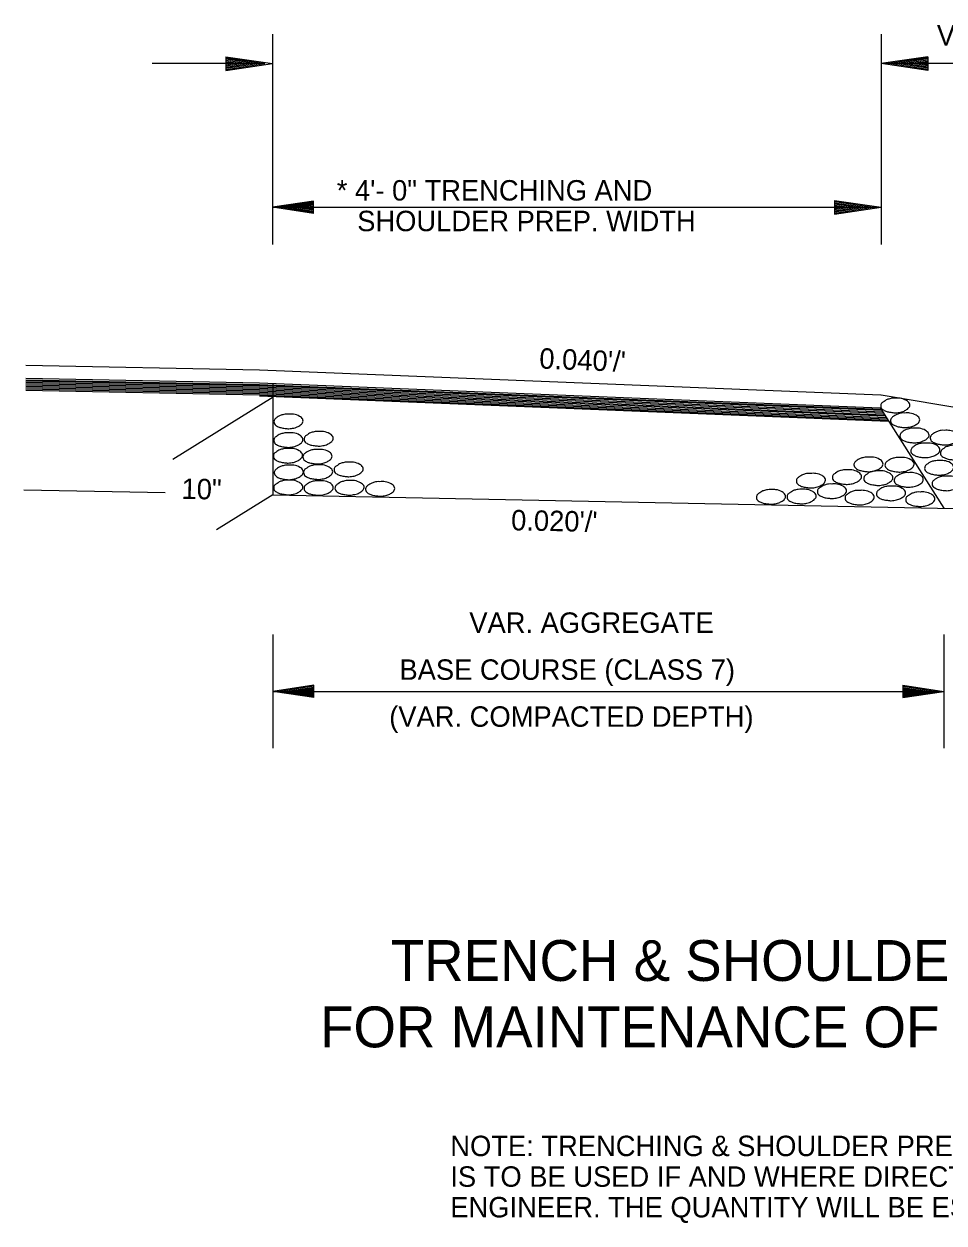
# Model space of a CAD drawing. Extents: x 1929624 to 1935547, y 596315 to 605721.
# Drawn here: x 1932720.6 to 1932990.8, y 604122.9 to 604475 of the extents above; entities that cross this region are included whole.
import ezdxf

# ---------------------------------------------------------------- set-up
doc = ezdxf.new("R2010")
doc.units = 0
doc.layers.add('Default', color=7, linetype='Continuous')
doc.layers.add('R_Border', color=7, linetype='Continuous')

msp = doc.modelspace()

# ---------------------------------------------------------------- linework, layer by layer
at = {"layer": 'Default'}
for p, q in [((1932793.63, 604472.05), (1932793.63, 604410.28)), ((1932972.32, 604472.05), (1932972.32, 604410.28)), ((1932791.33, 604463.38), (1932758.3, 604463.38)), ((1932779.9, 604465.42), (1932793.6, 604463.38)), ((1932779.9, 604465.42), (1932779.9, 604461.32)), ((1932779.9, 604465.09), (1932791.33, 604463.38)), ((1932779.9, 604464.74), (1932788.96, 604463.38)), ((1932779.9, 604464.41), (1932786.68, 604463.38)), ((1932779.9, 604464.02), (1932784.36, 604463.38)), ((1932779.9, 604463.71), (1932782.09, 604463.38)), ((1932779.9, 604461.32), (1932793.6, 604463.38)), ((1932779.9, 604462.7), (1932784.36, 604463.38)), ((1932779.9, 604462.01), (1932788.96, 604463.38)), ((1932779.9, 604461.67), (1932791.33, 604463.38)), ((1932779.9, 604462.37), (1932786.68, 604463.38)), ((1932779.9, 604463.05), (1932782.09, 604463.38)), ((1932986.02, 604465.42), (1932972.32, 604463.38)), ((1932986.02, 604461.32), (1932972.32, 604463.38)), ((1933213.06, 604463.38), (1932972.32, 604463.38)), ((1932986.02, 604465.09), (1932974.59, 604463.38)), ((1932986.02, 604461.67), (1932974.59, 604463.38)), ((1932986.02, 604464.74), (1932976.96, 604463.38)), ((1932986.02, 604462.01), (1932976.96, 604463.38)), ((1932986.02, 604464.41), (1932979.24, 604463.38)), ((1932986.02, 604462.37), (1932979.24, 604463.38)), ((1932986.02, 604464.02), (1932981.56, 604463.38)), ((1932986.02, 604462.7), (1932981.56, 604463.38)), ((1932986.02, 604463.71), (1932983.83, 604463.38)), ((1932986.02, 604463.05), (1932983.83, 604463.38)), ((1932986.02, 604465.42), (1932986.02, 604461.32)), ((1932805.63, 604422.99), (1932793.63, 604421.19)), ((1932793.63, 604421.19), (1932972.32, 604421.19)), ((1932805.63, 604419.39), (1932793.63, 604421.19)), ((1932805.63, 604422.69), (1932795.63, 604421.19)), ((1932805.63, 604419.69), (1932795.63, 604421.19)), ((1932805.63, 604422.38), (1932797.7, 604421.19)), ((1932805.63, 604420), (1932797.7, 604421.19)), ((1932805.63, 604422.08), (1932799.7, 604421.19)), ((1932805.63, 604420.3), (1932799.7, 604421.19)), ((1932805.63, 604421.78), (1932801.73, 604421.19)), ((1932805.63, 604420.61), (1932801.73, 604421.19)), ((1932805.63, 604421.47), (1932803.73, 604421.19)), ((1932805.63, 604420.91), (1932803.73, 604421.19)), ((1932805.63, 604419.39), (1932805.63, 604422.99)), ((1932958.64, 604423.23), (1932972.32, 604421.19)), ((1932958.64, 604423.23), (1932958.64, 604419.13)), ((1932958.64, 604422.9), (1932970.03, 604421.19)), ((1932958.64, 604422.54), (1932967.69, 604421.19)), ((1932958.64, 604422.21), (1932965.42, 604421.19)), ((1932958.64, 604421.84), (1932963.06, 604421.19)), ((1932958.64, 604421.51), (1932960.79, 604421.19)), ((1932958.64, 604419.13), (1932972.32, 604421.19)), ((1932958.64, 604420.5), (1932963.06, 604421.19)), ((1932958.64, 604419.81), (1932967.69, 604421.19)), ((1932958.64, 604419.47), (1932970.03, 604421.19)), ((1932958.64, 604420.17), (1932965.42, 604421.19)), ((1932958.64, 604420.86), (1932960.79, 604421.19)), ((1932972.32, 604417.14), (1932972.32, 604410.28)), ((1932721.2, 604374.81), (1932789.81, 604373.44)), ((1932721.2, 604370.99), (1932789.81, 604369.64)), ((1932789.81, 604373.44), (1932972.2, 604366.13)), ((1932721.2, 604370.57), (1932789.81, 604369.2)), ((1932721.2, 604370.25), (1932789.81, 604368.87)), ((1932721.2, 604369.84), (1932789.81, 604368.45)), ((1932721.2, 604369.44), (1932789.81, 604368.03)), ((1932721.2, 604369.06), (1932789.81, 604367.67)), ((1932721.2, 604368.67), (1932789.81, 604367.29)), ((1932721.2, 604368.28), (1932789.81, 604366.91)), ((1932721.2, 604367.85), (1932789.81, 604366.49)), ((1932721.2, 604367.47), (1932789.81, 604366.12)), ((1932789.81, 604369.64), (1932972.04, 604362.31)), ((1932789.81, 604369.2), (1932972.32, 604361.86)), ((1932789.81, 604368.87), (1932972.51, 604361.57)), ((1932789.81, 604368.45), (1932972.82, 604361.11)), ((1932789.81, 604368.03), (1932973.04, 604360.71)), ((1932789.81, 604367.67), (1932973.32, 604360.27)), ((1932789.81, 604367.29), (1932973.54, 604359.93)), ((1932793.72, 604369.49), (1932793.72, 604336.78)), ((1932793.76, 604365.44), (1932764.33, 604347.1)), ((1932789.81, 604366.91), (1932973.86, 604359.49)), ((1932789.81, 604366.49), (1932974.1, 604359.09)), ((1932789.81, 604366.12), (1932974.36, 604358.65)), ((1932789.81, 604365.79), (1932974.53, 604358.37)), ((1932972.32, 604366.13), (1933363.55, 604300.92)), ((1932972.04, 604362.31), (1932990.74, 604332.85)), ((1932720.62, 604338.25), (1932762.1, 604337.42)), ((1932793.72, 604336.78), (1932777.18, 604326.47)), ((1932793.72, 604336.78), (1933196.64, 604328.73)), ((1932793.72, 604295.7), (1932793.72, 604262.34)), ((1932990.74, 604295.7), (1932990.74, 604262.34)), ((1932805.72, 604280.82), (1932793.72, 604279.02)), ((1932805.72, 604280.52), (1932795.72, 604279.02)), ((1932805.72, 604280.21), (1932797.79, 604279.02)), ((1932805.72, 604279.91), (1932799.79, 604279.02)), ((1932805.72, 604279.61), (1932801.82, 604279.02)), ((1932805.72, 604279.3), (1932803.82, 604279.02)), ((1932805.72, 604277.22), (1932805.72, 604280.82)), ((1932978.74, 604280.82), (1932990.74, 604279.02)), ((1932978.74, 604280.82), (1932978.74, 604277.22)), ((1932978.74, 604280.52), (1932988.74, 604279.02)), ((1932978.74, 604280.21), (1932986.67, 604279.02)), ((1932978.74, 604279.91), (1932984.67, 604279.02)), ((1932978.74, 604279.6), (1932982.64, 604279.02)), ((1932978.74, 604279.3), (1932980.64, 604279.02)), ((1932793.72, 604279.02), (1932990.74, 604279.02)), ((1932805.72, 604277.22), (1932793.72, 604279.02)), ((1932805.72, 604277.52), (1932795.72, 604279.02)), ((1932805.72, 604277.83), (1932797.79, 604279.02)), ((1932805.72, 604278.13), (1932799.79, 604279.02)), ((1932805.72, 604278.44), (1932801.82, 604279.02)), ((1932805.72, 604278.74), (1932803.82, 604279.02)), ((1932978.74, 604277.22), (1932990.74, 604279.02)), ((1932978.74, 604278.43), (1932982.64, 604279.02)), ((1932978.74, 604277.83), (1932986.67, 604279.02)), ((1932978.74, 604277.52), (1932988.74, 604279.02)), ((1932978.74, 604278.13), (1932984.67, 604279.02)), ((1932978.74, 604278.74), (1932980.64, 604279.02))]:
    msp.add_line(p, q, dxfattribs=at)
for points in [[(1932976.42, 604365.1), (1932977.95, 604365.09), (1932979.77, 604364.45), (1932980.66, 604363.62), (1932980.78, 604363.08), (1932980.32, 604362.16), (1932979.8, 604361.77), (1932978.8, 604361.25), (1932977.34, 604360.91), (1932976.58, 604360.83), (1932975.47, 604360.94), (1932974.21, 604361.15), (1932973.26, 604361.52), (1932972.38, 604362.25), (1932972.23, 604362.83), (1932972.49, 604363.65), (1932973.19, 604364.18), (1932973.83, 604364.6), (1932974.85, 604364.95), (1932975.48, 604365.09), (1932976.42, 604365.1)], [(1932798.22, 604360.43), (1932799.75, 604360.42), (1932801.57, 604359.78), (1932802.46, 604358.95), (1932802.58, 604358.41), (1932802.12, 604357.49), (1932801.6, 604357.1), (1932800.6, 604356.58), (1932799.14, 604356.24), (1932798.38, 604356.16), (1932797.27, 604356.27), (1932796.01, 604356.48), (1932795.06, 604356.85), (1932794.18, 604357.58), (1932794.03, 604358.16), (1932794.29, 604358.98), (1932794.99, 604359.51), (1932795.63, 604359.93), (1932796.65, 604360.28), (1932797.28, 604360.42), (1932798.22, 604360.43)], [(1932979.3, 604360.77), (1932980.8, 604360.76), (1932982.62, 604360.12), (1932983.54, 604359.28), (1932983.67, 604358.75), (1932983.18, 604357.83), (1932982.64, 604357.41), (1932981.69, 604356.91), (1932980.17, 604356.6), (1932979.44, 604356.49), (1932978.3, 604356.61), (1932977.09, 604356.81), (1932976.15, 604357.2), (1932975.25, 604357.89), (1932975.09, 604358.5), (1932975.38, 604359.31), (1932976.06, 604359.87), (1932976.72, 604360.29), (1932977.7, 604360.6), (1932978.32, 604360.76), (1932979.3, 604360.77)], [(1932798.18, 604354.95), (1932799.71, 604354.94), (1932801.53, 604354.3), (1932802.42, 604353.47), (1932802.54, 604352.93), (1932802.08, 604352.01), (1932801.56, 604351.62), (1932800.56, 604351.1), (1932799.1, 604350.76), (1932798.34, 604350.68), (1932797.23, 604350.79), (1932795.97, 604351), (1932795.02, 604351.37), (1932794.14, 604352.1), (1932793.99, 604352.68), (1932794.25, 604353.5), (1932794.95, 604354.03), (1932795.59, 604354.45), (1932796.61, 604354.8), (1932797.24, 604354.94), (1932798.18, 604354.95)], [(1932807.08, 604355.33), (1932808.61, 604355.32), (1932810.43, 604354.68), (1932811.32, 604353.85), (1932811.44, 604353.31), (1932810.98, 604352.39), (1932810.46, 604352), (1932809.46, 604351.48), (1932808, 604351.14), (1932807.24, 604351.06), (1932806.13, 604351.17), (1932804.87, 604351.38), (1932803.92, 604351.75), (1932803.04, 604352.48), (1932802.89, 604353.06), (1932803.15, 604353.88), (1932803.85, 604354.41), (1932804.49, 604354.83), (1932805.51, 604355.18), (1932806.14, 604355.32), (1932807.08, 604355.33)], [(1932982.06, 604356.3), (1932983.57, 604356.28), (1932985.38, 604355.66), (1932986.28, 604354.79), (1932986.44, 604354.29), (1932985.96, 604353.35), (1932985.43, 604352.93), (1932984.44, 604352.48), (1932982.96, 604352.09), (1932982.2, 604352.03), (1932981.08, 604352.11), (1932979.85, 604352.33), (1932978.9, 604352.71), (1932978.02, 604353.42), (1932977.87, 604354.02), (1932978.13, 604354.82), (1932978.82, 604355.4), (1932979.46, 604355.83), (1932980.49, 604356.14), (1932981.11, 604356.28), (1932982.06, 604356.3)], [(1932990.96, 604355.68), (1932992.47, 604355.66), (1932994.28, 604355.04), (1932995.2, 604354.16), (1932995.31, 604353.68), (1932994.85, 604352.73), (1932994.32, 604352.33), (1932993.34, 604351.84), (1932991.85, 604351.47), (1932991.1, 604351.41), (1932989.98, 604351.52), (1932988.75, 604351.72), (1932987.78, 604352.09), (1932986.91, 604352.82), (1932986.75, 604353.4), (1932987.02, 604354.21), (1932987.72, 604354.77), (1932988.36, 604355.19), (1932989.38, 604355.52), (1932989.99, 604355.66), (1932990.96, 604355.68)], [(1932798.06, 604350.35), (1932799.59, 604350.34), (1932801.41, 604349.7), (1932802.3, 604348.87), (1932802.42, 604348.33), (1932801.96, 604347.41), (1932801.44, 604347.02), (1932800.44, 604346.5), (1932798.98, 604346.16), (1932798.22, 604346.08), (1932797.11, 604346.19), (1932795.85, 604346.4), (1932794.9, 604346.77), (1932794.02, 604347.5), (1932793.87, 604348.08), (1932794.13, 604348.9), (1932794.83, 604349.43), (1932795.47, 604349.85), (1932796.49, 604350.2), (1932797.12, 604350.34), (1932798.06, 604350.35)], [(1932806.72, 604350.08), (1932808.25, 604350.07), (1932810.07, 604349.43), (1932810.96, 604348.6), (1932811.08, 604348.06), (1932810.62, 604347.14), (1932810.1, 604346.75), (1932809.1, 604346.23), (1932807.64, 604345.89), (1932806.88, 604345.81), (1932805.77, 604345.92), (1932804.51, 604346.13), (1932803.56, 604346.5), (1932802.68, 604347.23), (1932802.53, 604347.81), (1932802.79, 604348.63), (1932803.49, 604349.16), (1932804.13, 604349.58), (1932805.15, 604349.93), (1932805.78, 604350.07), (1932806.72, 604350.08)], [(1932985.27, 604351.92), (1932986.75, 604351.9), (1932988.59, 604351.31), (1932989.46, 604350.44), (1932989.62, 604349.94), (1932989.15, 604348.99), (1932988.61, 604348.59), (1932987.62, 604348.12), (1932986.16, 604347.74), (1932985.38, 604347.68), (1932984.27, 604347.76), (1932983.04, 604347.96), (1932982.09, 604348.37), (1932981.19, 604349.08), (1932981.06, 604349.65), (1932981.33, 604350.47), (1932982.01, 604351.02), (1932982.64, 604351.45), (1932983.67, 604351.8), (1932984.29, 604351.9), (1932985.27, 604351.92)], [(1932993.98, 604351.28), (1932995.46, 604351.27), (1932997.3, 604350.64), (1932998.17, 604349.77), (1932998.33, 604349.27), (1932997.86, 604348.34), (1932997.32, 604347.93), (1932996.33, 604347.45), (1932994.87, 604347.07), (1932994.09, 604347.03), (1932993, 604347.09), (1932991.75, 604347.29), (1932990.8, 604347.7), (1932989.91, 604348.4), (1932989.77, 604348.99), (1932990.05, 604349.82), (1932990.74, 604350.38), (1932991.35, 604350.81), (1932992.38, 604351.11), (1932993.02, 604351.27), (1932993.98, 604351.28)], [(1932815.88, 604346.33), (1932817.41, 604346.32), (1932819.23, 604345.68), (1932820.12, 604344.85), (1932820.24, 604344.31), (1932819.78, 604343.39), (1932819.26, 604343), (1932818.26, 604342.48), (1932816.8, 604342.14), (1932816.04, 604342.06), (1932814.93, 604342.17), (1932813.67, 604342.38), (1932812.72, 604342.75), (1932811.84, 604343.48), (1932811.69, 604344.06), (1932811.95, 604344.88), (1932812.65, 604345.41), (1932813.29, 604345.83), (1932814.31, 604346.18), (1932814.94, 604346.32), (1932815.88, 604346.33)], [(1932968.54, 604347.81), (1932970.07, 604347.8), (1932971.89, 604347.16), (1932972.78, 604346.33), (1932972.9, 604345.79), (1932972.44, 604344.87), (1932971.92, 604344.48), (1932970.92, 604343.96), (1932969.46, 604343.62), (1932968.7, 604343.54), (1932967.59, 604343.65), (1932966.33, 604343.86), (1932965.38, 604344.23), (1932964.5, 604344.96), (1932964.35, 604345.54), (1932964.61, 604346.36), (1932965.31, 604346.89), (1932965.95, 604347.31), (1932966.97, 604347.66), (1932967.6, 604347.8), (1932968.54, 604347.81)], [(1932977.66, 604347.71), (1932979.19, 604347.7), (1932981.01, 604347.06), (1932981.9, 604346.23), (1932982.02, 604345.69), (1932981.56, 604344.77), (1932981.04, 604344.38), (1932980.04, 604343.86), (1932978.58, 604343.52), (1932977.82, 604343.44), (1932976.71, 604343.55), (1932975.45, 604343.76), (1932974.5, 604344.13), (1932973.62, 604344.86), (1932973.47, 604345.44), (1932973.73, 604346.26), (1932974.43, 604346.79), (1932975.07, 604347.21), (1932976.09, 604347.56), (1932976.72, 604347.7), (1932977.66, 604347.71)], [(1932989.29, 604346.82), (1932990.83, 604346.78), (1932992.66, 604346.17), (1932993.55, 604345.3), (1932993.65, 604344.8), (1932993.19, 604343.85), (1932992.67, 604343.44), (1932991.69, 604342.96), (1932990.21, 604342.6), (1932989.45, 604342.54), (1932988.34, 604342.63), (1932987.12, 604342.85), (1932986.16, 604343.22), (1932985.27, 604343.93), (1932985.11, 604344.53), (1932985.38, 604345.36), (1932986.07, 604345.89), (1932986.72, 604346.33), (1932987.72, 604346.65), (1932988.36, 604346.78), (1932989.29, 604346.82)], [(1932798.31, 604345.46), (1932799.84, 604345.45), (1932801.66, 604344.81), (1932802.55, 604343.98), (1932802.67, 604343.44), (1932802.21, 604342.52), (1932801.69, 604342.13), (1932800.69, 604341.61), (1932799.23, 604341.27), (1932798.47, 604341.19), (1932797.36, 604341.3), (1932796.1, 604341.51), (1932795.15, 604341.88), (1932794.27, 604342.61), (1932794.12, 604343.19), (1932794.38, 604344.01), (1932795.08, 604344.54), (1932795.72, 604344.96), (1932796.74, 604345.31), (1932797.37, 604345.45), (1932798.31, 604345.46)], [(1932806.91, 604345.54), (1932808.44, 604345.53), (1932810.26, 604344.89), (1932811.15, 604344.06), (1932811.27, 604343.52), (1932810.81, 604342.6), (1932810.29, 604342.21), (1932809.29, 604341.69), (1932807.83, 604341.35), (1932807.07, 604341.27), (1932805.96, 604341.38), (1932804.7, 604341.59), (1932803.75, 604341.96), (1932802.87, 604342.69), (1932802.72, 604343.27), (1932802.98, 604344.09), (1932803.68, 604344.62), (1932804.32, 604345.04), (1932805.34, 604345.39), (1932805.97, 604345.53), (1932806.91, 604345.54)], [(1932951.63, 604343.04), (1932953.16, 604343.03), (1932954.98, 604342.39), (1932955.87, 604341.56), (1932955.99, 604341.02), (1932955.53, 604340.1), (1932955.01, 604339.71), (1932954.01, 604339.19), (1932952.55, 604338.85), (1932951.79, 604338.77), (1932950.68, 604338.88), (1932949.42, 604339.09), (1932948.47, 604339.46), (1932947.59, 604340.19), (1932947.44, 604340.77), (1932947.7, 604341.59), (1932948.4, 604342.12), (1932949.04, 604342.54), (1932950.06, 604342.89), (1932950.69, 604343.03), (1932951.63, 604343.04)], [(1932962.21, 604344.08), (1932963.74, 604344.07), (1932965.56, 604343.43), (1932966.45, 604342.6), (1932966.57, 604342.06), (1932966.11, 604341.14), (1932965.59, 604340.75), (1932964.59, 604340.23), (1932963.13, 604339.89), (1932962.37, 604339.81), (1932961.26, 604339.92), (1932960, 604340.13), (1932959.05, 604340.5), (1932958.17, 604341.23), (1932958.02, 604341.81), (1932958.28, 604342.63), (1932958.98, 604343.16), (1932959.62, 604343.58), (1932960.64, 604343.93), (1932961.27, 604344.07), (1932962.21, 604344.08)], [(1932971.44, 604343.77), (1932972.97, 604343.76), (1932974.79, 604343.12), (1932975.68, 604342.29), (1932975.8, 604341.75), (1932975.34, 604340.83), (1932974.82, 604340.44), (1932973.82, 604339.92), (1932972.36, 604339.58), (1932971.6, 604339.5), (1932970.49, 604339.61), (1932969.23, 604339.82), (1932968.28, 604340.19), (1932967.4, 604340.92), (1932967.25, 604341.5), (1932967.51, 604342.32), (1932968.21, 604342.85), (1932968.85, 604343.27), (1932969.87, 604343.62), (1932970.5, 604343.76), (1932971.44, 604343.77)], [(1932980.36, 604343.25), (1932981.89, 604343.24), (1932983.71, 604342.6), (1932984.6, 604341.77), (1932984.72, 604341.23), (1932984.26, 604340.31), (1932983.74, 604339.92), (1932982.74, 604339.4), (1932981.28, 604339.06), (1932980.52, 604338.98), (1932979.41, 604339.09), (1932978.15, 604339.3), (1932977.2, 604339.67), (1932976.32, 604340.4), (1932976.17, 604340.98), (1932976.43, 604341.8), (1932977.13, 604342.33), (1932977.77, 604342.75), (1932978.79, 604343.1), (1932979.42, 604343.24), (1932980.36, 604343.25)], [(1932798.15, 604341.02), (1932799.68, 604341.01), (1932801.5, 604340.37), (1932802.39, 604339.54), (1932802.51, 604339), (1932802.05, 604338.08), (1932801.53, 604337.69), (1932800.53, 604337.17), (1932799.07, 604336.83), (1932798.31, 604336.75), (1932797.2, 604336.86), (1932795.94, 604337.07), (1932794.99, 604337.44), (1932794.11, 604338.17), (1932793.96, 604338.75), (1932794.22, 604339.57), (1932794.92, 604340.1), (1932795.56, 604340.52), (1932796.58, 604340.87), (1932797.21, 604341.01), (1932798.15, 604341.02)], [(1932807.07, 604340.88), (1932808.6, 604340.87), (1932810.42, 604340.23), (1932811.31, 604339.4), (1932811.43, 604338.86), (1932810.97, 604337.94), (1932810.45, 604337.55), (1932809.45, 604337.03), (1932807.99, 604336.69), (1932807.23, 604336.61), (1932806.12, 604336.72), (1932804.86, 604336.93), (1932803.91, 604337.3), (1932803.03, 604338.03), (1932802.88, 604338.61), (1932803.14, 604339.43), (1932803.84, 604339.96), (1932804.48, 604340.38), (1932805.5, 604340.73), (1932806.13, 604340.87), (1932807.07, 604340.88)], [(1932816.14, 604340.93), (1932817.67, 604340.92), (1932819.49, 604340.28), (1932820.38, 604339.45), (1932820.5, 604338.91), (1932820.04, 604337.99), (1932819.52, 604337.6), (1932818.52, 604337.08), (1932817.06, 604336.74), (1932816.3, 604336.66), (1932815.19, 604336.77), (1932813.93, 604336.98), (1932812.98, 604337.35), (1932812.1, 604338.08), (1932811.95, 604338.66), (1932812.21, 604339.48), (1932812.91, 604340.01), (1932813.55, 604340.43), (1932814.57, 604340.78), (1932815.2, 604340.92), (1932816.14, 604340.93)], [(1932825.13, 604340.61), (1932826.66, 604340.6), (1932828.48, 604339.96), (1932829.37, 604339.13), (1932829.49, 604338.59), (1932829.03, 604337.67), (1932828.51, 604337.28), (1932827.51, 604336.76), (1932826.05, 604336.42), (1932825.29, 604336.34), (1932824.18, 604336.45), (1932822.92, 604336.66), (1932821.97, 604337.03), (1932821.09, 604337.76), (1932820.94, 604338.34), (1932821.2, 604339.16), (1932821.9, 604339.69), (1932822.54, 604340.11), (1932823.56, 604340.46), (1932824.19, 604340.6), (1932825.13, 604340.61)], [(1932957.81, 604339.93), (1932959.34, 604339.92), (1932961.16, 604339.28), (1932962.05, 604338.45), (1932962.17, 604337.91), (1932961.71, 604336.99), (1932961.19, 604336.6), (1932960.19, 604336.08), (1932958.73, 604335.74), (1932957.97, 604335.66), (1932956.86, 604335.77), (1932955.6, 604335.98), (1932954.65, 604336.35), (1932953.77, 604337.08), (1932953.62, 604337.66), (1932953.88, 604338.48), (1932954.58, 604339.01), (1932955.22, 604339.43), (1932956.24, 604339.78), (1932956.87, 604339.92), (1932957.81, 604339.93)], [(1932975.16, 604339.3), (1932976.69, 604339.29), (1932978.51, 604338.65), (1932979.4, 604337.82), (1932979.52, 604337.28), (1932979.06, 604336.36), (1932978.54, 604335.97), (1932977.54, 604335.45), (1932976.08, 604335.11), (1932975.32, 604335.03), (1932974.21, 604335.14), (1932972.95, 604335.35), (1932972, 604335.72), (1932971.12, 604336.45), (1932970.97, 604337.03), (1932971.23, 604337.85), (1932971.93, 604338.38), (1932972.57, 604338.8), (1932973.59, 604339.15), (1932974.22, 604339.29), (1932975.16, 604339.3)], [(1932991.46, 604342.26), (1932993, 604342.21), (1932994.82, 604341.6), (1932995.71, 604340.73), (1932995.82, 604340.23), (1932995.35, 604339.28), (1932994.84, 604338.88), (1932993.86, 604338.39), (1932992.38, 604338.04), (1932991.61, 604337.97), (1932990.51, 604338.07), (1932989.29, 604338.29), (1932988.32, 604338.66), (1932987.44, 604339.36), (1932987.28, 604339.97), (1932987.55, 604340.79), (1932988.23, 604341.32), (1932988.89, 604341.76), (1932989.88, 604342.09), (1932990.52, 604342.21), (1932991.46, 604342.26)], [(1932939.92, 604338.27), (1932941.45, 604338.26), (1932943.27, 604337.62), (1932944.16, 604336.79), (1932944.28, 604336.25), (1932943.82, 604335.33), (1932943.3, 604334.94), (1932942.3, 604334.42), (1932940.84, 604334.08), (1932940.08, 604334), (1932938.97, 604334.11), (1932937.71, 604334.32), (1932936.76, 604334.69), (1932935.88, 604335.42), (1932935.73, 604336), (1932935.99, 604336.82), (1932936.69, 604337.35), (1932937.33, 604337.77), (1932938.35, 604338.12), (1932938.98, 604338.26), (1932939.92, 604338.27)], [(1932948.9, 604338.37), (1932950.43, 604338.36), (1932952.25, 604337.72), (1932953.14, 604336.89), (1932953.26, 604336.35), (1932952.8, 604335.43), (1932952.28, 604335.04), (1932951.28, 604334.52), (1932949.82, 604334.18), (1932949.06, 604334.1), (1932947.95, 604334.21), (1932946.69, 604334.42), (1932945.74, 604334.79), (1932944.86, 604335.52), (1932944.71, 604336.1), (1932944.97, 604336.92), (1932945.67, 604337.45), (1932946.31, 604337.87), (1932947.33, 604338.22), (1932947.96, 604338.36), (1932948.9, 604338.37)], [(1932965.94, 604338.05), (1932967.47, 604338.04), (1932969.29, 604337.4), (1932970.18, 604336.57), (1932970.3, 604336.03), (1932969.84, 604335.11), (1932969.32, 604334.72), (1932968.32, 604334.2), (1932966.86, 604333.86), (1932966.1, 604333.78), (1932964.99, 604333.89), (1932963.73, 604334.1), (1932962.78, 604334.47), (1932961.9, 604335.2), (1932961.75, 604335.78), (1932962.01, 604336.6), (1932962.71, 604337.13), (1932963.35, 604337.55), (1932964.37, 604337.9), (1932965, 604338.04), (1932965.94, 604338.05)], [(1932983.75, 604337.58), (1932985.28, 604337.57), (1932987.1, 604336.93), (1932987.99, 604336.1), (1932988.11, 604335.56), (1932987.65, 604334.64), (1932987.13, 604334.25), (1932986.13, 604333.73), (1932984.67, 604333.39), (1932983.91, 604333.31), (1932982.8, 604333.42), (1932981.54, 604333.63), (1932980.59, 604334), (1932979.71, 604334.73), (1932979.56, 604335.31), (1932979.82, 604336.13), (1932980.52, 604336.66), (1932981.16, 604337.08), (1932982.18, 604337.43), (1932982.81, 604337.57), (1932983.75, 604337.58)]]:
    msp.add_spline(points, degree=3, dxfattribs=at)

# ---------------------------------------------------------------- texts
for s, height, p in [('VAR. WIDTH ACHM SURFACE COURSE (1/2")', 6, (1932988.71, 604468.7)), ('* 4\'- 0" TRENCHING AND ', 6, (1932812.47, 604423.17)), ('SHOULDER PREP. WIDTH ', 6, (1932818.47, 604414.17)), ('VAR. AGGREGATE', 6, (1932851.4, 604296.22)), ('BASE COURSE (CLASS 7)', 6, (1932830.88, 604282.43)), ('(VAR. COMPACTED DEPTH)', 6, (1932827.88, 604268.64)), ('TRENCH & SHOULDER PREP.', 12, (1932828.33, 604194)), ('FOR MAINTENANCE OF TRAFFIC', 12, (1932807.57, 604174.5))]:
    msp.add_text(s, height=height, dxfattribs=at).set_placement(p)
for s, rotation, p in [("0.040'/'", 357.7077, (1932871.86, 604373.86)), ('10"', 358.8543, (1932766.84, 604335.57)), ("0.020'/'", 358.8543, (1932863.63, 604326.35))]:
    msp.add_text(s, height=6, rotation=rotation, dxfattribs=at).set_placement(p)
at = {"layer": 'R_Border'}
for s, p in [('NOTE: TRENCHING & SHOULDER PREP. FOR MOT', (1932845.82, 604142.56)), ('IS TO BE USED IF AND WHERE DIRECTED BY THE', (1932845.82, 604133.56)), ('ENGINEER. THE QUANTITY WILL BE ESTIMATED.', (1932845.82, 604124.56))]:
    msp.add_text(s, height=6, rotation=360, dxfattribs=at).set_placement(p)

doc.saveas('drawing.dxf')
